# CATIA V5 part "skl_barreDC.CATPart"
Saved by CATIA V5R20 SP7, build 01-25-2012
Part number: skl_barreDC
Publications: "Axe pivot DC/Bati", "Axe pivot DC/BC", "Plan DC"
Bounding box of the stored display mesh (mm): x 0 to 0, y 60 to 72.665, z 0 to 18.428
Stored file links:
  U:\IAO_bon\skl_barreDC.CATPart
  U:\IAO_bon\skl_IAO.CATProduct
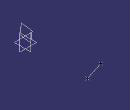
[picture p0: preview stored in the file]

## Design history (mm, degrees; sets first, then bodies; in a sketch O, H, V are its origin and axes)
Set1
  Point1 "Point D": linked copy from another document
  Point2 "Point C": linked copy from another document
  Plane1 "Plan Ref": linked copy from another document
Set2
  Line1: type PtPt, FirstPoint Point1, SecondPoint Point2
  Line2 "Axe pivot DC/Bati": type Normal, RefPoint Point1, RefSkin Plane1, Start 0, End 20
  Line3 "Axe pivot DC/BC": type Normal, RefPoint Point2, RefSkin Plane1, Start 0, End 20
  Plane2 "Plan DC": type Normal, Curve Line2, RefPoint Point1
Body1 (main body)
